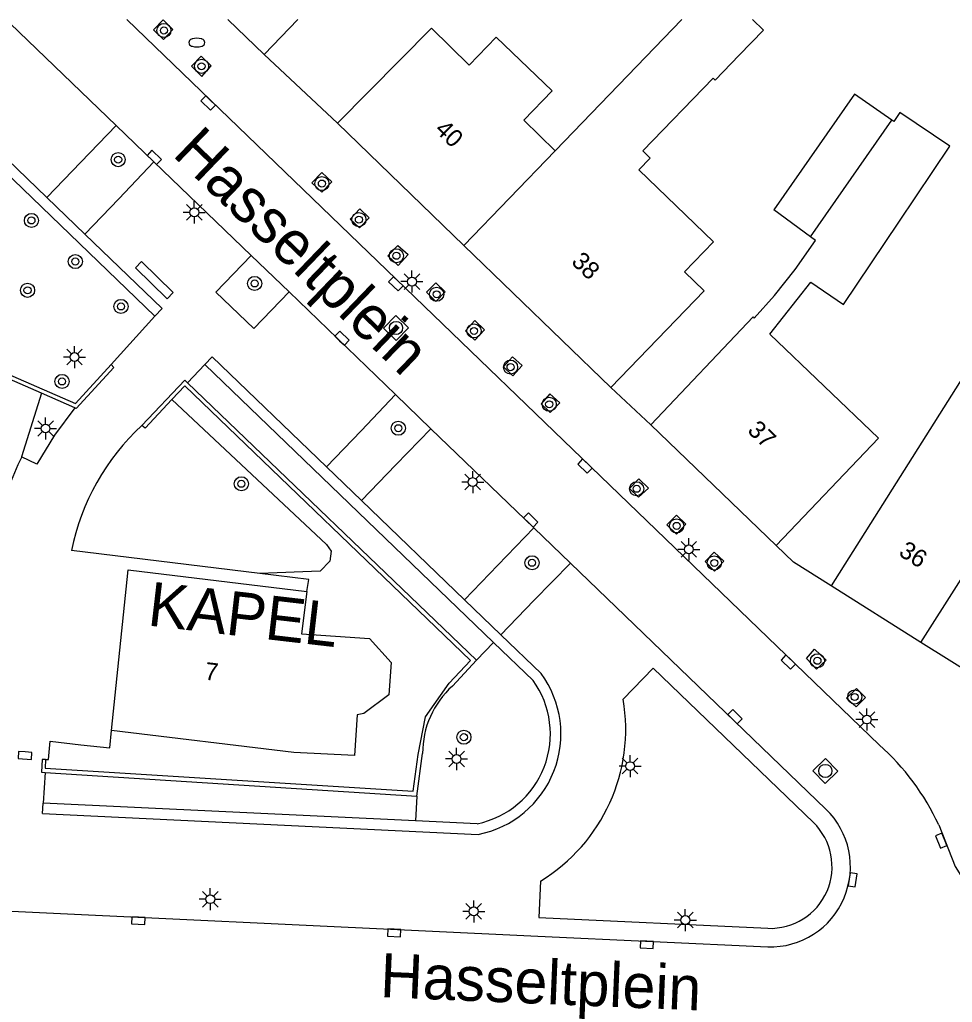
# Model space of a CAD drawing. Extents: x 132573 to 132944, y 398226 to 398676.
# Drawn here: x 132601.1 to 132654, y 398620.6 to 398676.3 of the extents above; entities that cross this region are included whole.
import ezdxf

# ---------------------------------------------------------------- set-up
doc = ezdxf.new("R2010")
doc.units = 0
for name, color, linetype in [('gg-afsc-muur', 7, 'Continuous'), ('gg-anno-huisnummerreeks BGT', 7, 'Continuous'), ('gg-anno-openbare ruimte label', 7, 'Continuous'), ('gg-bbg-gedigitaliseerde bebouwing', 7, 'Continuous'), ('gg-bbg-hoofdgebouw', 7, 'Continuous'), ('gg-bbg-tussenscheiding', 7, 'Continuous'), ('gg-knt-verharding', 7, 'Continuous'), ('gg-knt-verharding nz', 7, 'Continuous'), ('gt-anno-naam bijzondere bebouwing', 7, 'Continuous'), ('gt-grn-groengrens', 7, 'Continuous'), ('gt-symb-boom', 7, 'Continuous'), ('gt-symb-brandkraan', 7, 'Continuous'), ('gt-symb-kolk', 7, 'Continuous'), ('gt-symb-lichtmast', 7, 'Continuous'), ('gt-symb-rioolschacht', 7, 'Continuous')]:
    doc.layers.add(name, color=color, linetype=linetype)

msp = doc.modelspace()

# ---------------------------------------------------------------- linework, layer by layer
at = {"layer": 'gg-afsc-muur'}
for p, q in [((132626.969, 398640.013), (132610.591, 398655.743)), ((132604.184, 398654.336), (132602.3, 398655.159)), ((132625.614, 398638.552), (132626.969, 398640.013)), ((132623.589, 398632.31), (132623.919, 398634.733)), ((132602.5, 398633.653), (132623.589, 398632.31))]:
    msp.add_line(p, q, dxfattribs=at)
for points in [[(132581.916, 398656.875), (132582.123, 398657.394), (132586.774, 398662.172), (132604.239, 398654.571), (132606.249, 398656.783)], [(132602.3, 398655.159), (132586.814, 398661.924), (132582.315, 398657.245), (132580.926, 398653.711)], [(132606.249, 398656.783), (132606.396, 398656.624), (132604.276, 398654.296), (132604.184, 398654.336)], [(132602.536, 398634.387), (132602.516, 398633.899), (132623.377, 398632.584), (132623.666, 398634.661), (132624.092, 398636.807), (132625.425, 398638.709), (132626.629, 398640.007), (132610.43, 398655.572), (132609.699, 398654.797)], [(132610.591, 398655.743), (132610.43, 398655.897), (132607.998, 398653.329)], [(132609.699, 398654.797), (132608.176, 398653.182), (132607.998, 398653.329)], [(132602.536, 398634.387), (132602.332, 398634.387), (132602.292, 398633.666), (132602.5, 398633.653)]]:
    msp.add_lwpolyline(points, dxfattribs=at)
msp.add_arc((132629.062, 398634.736), 5.143, 132.0985, 180.035, dxfattribs=at)
at = {"layer": 'gg-bbg-gedigitaliseerde bebouwing'}
for p, q in [((132614.93, 398674.36), (132616.85, 398676.345)), ((132638.618, 398676.345), (132631.446, 398668.911)), ((132624.417, 398675.868), (132626.555, 398673.756)), ((132636.196, 398667.835), (132640.429, 398663.742)), ((132649.785, 398652.617), (132643.613, 398658.502))]:
    msp.add_line(p, q, dxfattribs=at)
for points in [[(132641.881, 398674.333), (132643.255, 398675.754), (132642.644, 398676.345)], [(132631.446, 398668.911), (132629.658, 398670.636), (132631.269, 398672.306), (132628.103, 398675.36), (132626.555, 398673.756)], [(132636.196, 398667.835), (132636.833, 398668.494), (132636.416, 398668.896), (132640.398, 398673.026), (132640.513, 398672.915), (132641.881, 398674.333)], [(132650.937, 398664.862), (132653.837, 398669.167), (132651.002, 398671.077), (132650.655, 398670.563), (132650.54, 398670.643)], [(132643.613, 398658.502), (132645.936, 398661.46), (132647.795, 398660.198), (132650.937, 398664.862)], [(132652.19, 398641.02), (132656.49, 398647.791), (132654.634, 398648.964), (132658.362, 398654.86), (132657.928, 398655.134), (132658.552, 398656.122), (132657.428, 398656.832), (132656.857, 398655.928), (132655.156, 398657.003), (132647.1, 398644.24)]]:
    msp.add_lwpolyline(points, dxfattribs=at)
at = {"layer": 'gg-bbg-hoofdgebouw'}
for p, q in [((132614.93, 398674.36), (132612.878, 398676.345)), ((132619.087, 398670.473), (132624.417, 398675.868)), ((132626.257, 398663.533), (132619.087, 398670.473)), ((132645.924, 398664.027), (132643.854, 398665.559)), ((132634.59, 398655.48), (132626.257, 398663.533)), ((132643.974, 398646.522), (132636.86, 398653.36)), ((132643.974, 398646.522), (132649.785, 398652.617)), ((132652.19, 398641.02), (132647.1, 398644.24))]:
    msp.add_line(p, q, dxfattribs=at)
for points in [[(132650.54, 398670.643), (132648.429, 398672.116), (132643.854, 398665.559)], [(132634.59, 398655.48), (132639.885, 398660.973), (132638.776, 398662.042), (132640.429, 398663.742)], [(132636.86, 398653.36), (132642.669, 398659.484), (132642.738, 398659.418), (132643.88, 398660.7), (132645.065, 398662.167), (132646.206, 398663.818), (132645.924, 398664.027)], [(132606.27, 398636.02), (132607.21, 398645.14), (132617.36, 398643.92)], [(132617.36, 398643.92), (132617.05, 398641.51), (132620.91, 398641.24), (132622.14, 398639.89), (132622, 398638.05), (132620.59, 398637), (132620.21, 398636.92), (132620.06, 398634.61), (132616.62, 398634.79), (132606.27, 398636.02)]]:
    msp.add_lwpolyline(points, dxfattribs=at)
at = {"layer": 'gg-bbg-tussenscheiding'}
for p, q in [((132645.924, 398664.027), (132650.54, 398670.643)), ((132631.446, 398668.911), (132626.257, 398663.533))]:
    msp.add_line(p, q, dxfattribs=at)
at = {"layer": 'gg-knt-verharding'}
for p, q in [((132600.53, 398676.126), (132606.54, 398670.339)), ((132607.145, 398676.345), (132649.82, 398635.22)), ((132619.087, 398670.473), (132614.93, 398674.36)), ((132596.587, 398672.048), (132602.603, 398666.258)), ((132604.538, 398668.268), (132606.54, 398670.339)), ((132606.54, 398670.339), (132608.669, 398668.288)), ((132604.538, 398668.268), (132602.603, 398666.258)), ((132608.669, 398668.288), (132606.693, 398666.186)), ((132608.669, 398668.288), (132614.197, 398662.965)), ((132602.603, 398666.258), (132604.762, 398664.18)), ((132606.693, 398666.186), (132604.762, 398664.18)), ((132604.762, 398664.18), (132609.141, 398659.964)), ((132614.197, 398662.965), (132616.343, 398660.899)), ((132616.343, 398660.899), (132622.378, 398655.087)), ((132608.737, 398659.52), (132609.141, 398659.964)), ((132606.249, 398656.783), (132608.737, 398659.52)), ((132611.575, 398656.787), (132611.987, 398657.223)), ((132618.47, 398650.983), (132611.987, 398657.223)), ((132610.591, 398655.743), (132611.575, 398656.787)), ((132634.59, 398655.48), (132636.86, 398653.36)), ((132620.431, 398653.02), (132622.378, 398655.087)), ((132622.378, 398655.087), (132624.397, 398653.143)), ((132620.431, 398653.02), (132618.47, 398650.983)), ((132624.397, 398653.143), (132622.397, 398651.093)), ((132624.397, 398653.143), (132630.228, 398647.528)), ((132620.453, 398649.074), (132618.47, 398650.983)), ((132622.397, 398651.093), (132620.453, 398649.074)), ((132626.299, 398643.446), (132620.453, 398649.074)), ((132628.182, 398645.402), (132630.228, 398647.528)), ((132630.228, 398647.528), (132632.317, 398645.516)), ((132614.689, 398644.939), (132604.005, 398646.24)), ((132628.182, 398645.402), (132626.299, 398643.446)), ((132632.317, 398645.516), (132630.235, 398643.407)), ((132646.8, 398631.57), (132632.317, 398645.516)), ((132628.362, 398641.461), (132626.299, 398643.446)), ((132630.235, 398643.407), (132628.362, 398641.461)), ((132630.641, 398639.267), (132628.362, 398641.461)), ((132656.431, 398638.37), (132652.19, 398641.02)), ((132602.5, 398633.653), (132602.39, 398631.917)), ((132602.352, 398631.318), (132602.39, 398631.917)), ((132602.352, 398631.318), (132627.07, 398630.14)), ((132630.61, 398627.49), (132630.51, 398625.42)), ((132630.51, 398625.42), (132643.502, 398624.81)), ((132630.462, 398624.371), (132643.504, 398623.758))]:
    msp.add_line(p, q, dxfattribs=at)
for points in [[(132609.222, 398675.228), (132608.658, 398675.768), (132609.201, 398676.328), (132609.745, 398675.793), (132609.222, 398675.228)], [(132611.397, 398673.13), (132611.932, 398673.727), (132611.35, 398674.27), (132610.817, 398673.703), (132611.397, 398673.13)], [(132617.637, 398667.088), (132618.198, 398666.567), (132618.769, 398667.145), (132618.197, 398667.68), (132617.637, 398667.088)], [(132619.804, 398665.035), (132620.354, 398665.615), (132620.888, 398665.099), (132620.343, 398664.535), (132619.804, 398665.035)], [(132621.946, 398662.943), (132622.514, 398663.542), (132623.094, 398663.031), (132622.543, 398662.406), (132621.946, 398662.943)], [(132616.343, 398660.899), (132614.346, 398658.829), (132612.188, 398660.895), (132614.197, 398662.965)], [(132624.136, 398660.881), (132624.664, 398660.364), (132625.193, 398660.904), (132624.665, 398661.422), (132624.136, 398660.881)], [(132626.353, 398658.7), (132626.882, 398659.28), (132627.436, 398658.757), (132626.882, 398658.171), (132626.353, 398658.7)], [(132628.504, 398656.653), (132629.02, 398657.219), (132629.562, 398656.73), (132629.034, 398656.144), (132628.504, 398656.653)], [(132630.645, 398654.563), (132631.164, 398654.062), (132631.698, 398654.615), (132631.142, 398655.115), (132630.645, 398654.563)], [(132604.184, 398654.336), (132603.035, 398652.785), (132602.039, 398651.132), (132601.175, 398651.558)], [(132635.655, 398649.748), (132636.179, 398650.298), (132636.735, 398649.778), (132636.177, 398649.264), (132635.655, 398649.748)], [(132637.778, 398647.694), (132638.318, 398648.251), (132638.858, 398647.728), (132638.318, 398647.171), (132637.778, 398647.694)], [(132647.1, 398644.24), (132644.96, 398645.58), (132643.974, 398646.522)], [(132639.947, 398645.605), (132640.48, 398645.06), (132641.015, 398645.629), (132640.461, 398646.151), (132639.947, 398645.605)], [(132617.36, 398643.92), (132617.474, 398644.6), (132614.689, 398644.939)], [(132645.691, 398640.113), (132646.16, 398640.648), (132646.811, 398640.024), (132646.275, 398639.514), (132645.691, 398640.113)], [(132646.09, 398630.81), (132637.01, 398639.57), (132635.3, 398637.798)], [(132647.976, 398637.865), (132648.512, 398637.373), (132649.046, 398637.896), (132648.535, 398638.415), (132647.976, 398637.865)], [(132604.528, 398635.224), (132606.169, 398635.04), (132606.27, 398636.02)], [(132602.536, 398634.387), (132602.691, 398634.386), (132602.8, 398635.418), (132604.528, 398635.224)], [(132653.2, 398630.67), (132654.14, 398628.31), (132656.12, 398625.15)], [(132595.275, 398623.27), (132595.4, 398626.02), (132630.462, 398624.371)]]:
    msp.add_lwpolyline(points, dxfattribs=at)
for centre, radius, start, end in [((132616.971, 398643.606), 13.23, 132.7013, 168.5165), ((132617.338, 398643.698), 17.972, 154.0661, 166.8003), ((132625.971, 398635.832), 5.797, 280.9241, 36.3394), ((132625.374, 398636.093), 10.071, 301.3235, 9.7467), ((132640.708, 398624.921), 13.751, 24.7137, 48.5005), ((132643.647, 398628.299), 4.543, 268.1983, 46.0505), ((132643.653, 398628.303), 3.496, 267.5301, 45.8056)]:
    msp.add_arc(centre, radius, start, end, dxfattribs=at)
at = {"layer": 'gg-knt-verharding nz'}
msp.add_lwpolyline([(132609.426, 398660.505), (132609.767, 398660.868), (132607.969, 398662.628), (132607.629, 398662.265), (132609.426, 398660.505)], dxfattribs=at)
at = {"layer": 'gt-grn-groengrens'}
for p, q in [((132627.946, 398641.028), (132611.575, 398656.787)), ((132602.3, 398655.159), (132601.175, 398651.558)), ((132626.969, 398640.013), (132627.946, 398641.028)), ((132630.187, 398638.871), (132627.946, 398641.028)), ((132623.589, 398632.31), (132623.522, 398630.91)), ((132623.522, 398630.91), (132602.39, 398631.917)), ((132627.025, 398630.743), (132623.522, 398630.91))]:
    msp.add_line(p, q, dxfattribs=at)
for points in [[(132608.737, 398659.52), (132594.261, 398673.455), (132580.619, 398659.429)], [(132609.699, 398654.797), (132618.478, 398646.576), (132618.732, 398646.208), (132618.665, 398645.628), (132618.106, 398645.068), (132614.689, 398644.939)]]:
    msp.add_lwpolyline(points, dxfattribs=at)
msp.add_arc((132625.972, 398635.832), 5.197, 281.6925, 35.7929, dxfattribs=at)
at = {"layer": 'gt-symb-boom'}
for centre, radius in [((132609.246, 398675.731), 0.4), ((132609.246, 398675.731), 0.2), ((132611.378, 398673.7), 0.4), ((132611.378, 398673.7), 0.2), ((132606.65, 398668.406), 0.4), ((132606.65, 398668.406), 0.2), ((132618.207, 398667.049), 0.4), ((132618.207, 398667.049), 0.2), ((132601.731, 398664.957), 0.4), ((132601.731, 398664.957), 0.2), ((132620.305, 398665.002), 0.4), ((132620.305, 398665.002), 0.2), ((132622.438, 398662.953), 0.4), ((132604.22, 398662.628), 0.4), ((132604.22, 398662.628), 0.2), ((132622.438, 398662.953), 0.2), ((132614.392, 398661.385), 0.4), ((132614.392, 398661.385), 0.2), ((132601.508, 398660.994), 0.4), ((132601.508, 398660.994), 0.2), ((132624.717, 398660.77), 0.4), ((132624.717, 398660.77), 0.2), ((132606.809, 398660.08), 0.4), ((132606.809, 398660.08), 0.2), ((132626.837, 398658.69), 0.4), ((132626.837, 398658.69), 0.2), ((132628.91, 398656.637), 0.4), ((132628.91, 398656.637), 0.2), ((132603.465, 398655.825), 0.4), ((132603.465, 398655.825), 0.2), ((132631.102, 398654.532), 0.4), ((132631.102, 398654.532), 0.2), ((132622.543, 398653.172), 0.4), ((132622.543, 398653.172), 0.2), ((132613.639, 398650.023), 0.4), ((132613.639, 398650.023), 0.2), ((132636.063, 398649.739), 0.4), ((132636.063, 398649.739), 0.2), ((132638.332, 398647.635), 0.4), ((132638.332, 398647.635), 0.2), ((132630.128, 398645.54), 0.4), ((132640.468, 398645.532), 0.4), ((132630.128, 398645.54), 0.2), ((132640.468, 398645.532), 0.2), ((132646.32, 398639.983), 0.4), ((132646.32, 398639.983), 0.2), ((132648.435, 398637.931), 0.4), ((132648.435, 398637.931), 0.2), ((132626.261, 398635.651), 0.4), ((132626.261, 398635.651), 0.2)]:
    msp.add_circle(centre, radius, dxfattribs=at)
at = {"layer": 'gt-symb-brandkraan'}
for centre, radius, start, end in [((132610.871, 398675.045), 0.206, 107.5669, 252.4331), ((132611.714, 398672.381), 3, 106.892, 107.5669), ((132611.115, 398674.354), 0.938, 73.108, 106.892), ((132610.516, 398672.381), 3, 72.4331, 73.108), ((132611.359, 398675.045), 0.206, 287.567, 72.4331), ((132611.714, 398677.709), 3, 252.4331, 253.108), ((132611.115, 398675.736), 0.938, 253.108, 286.8921), ((132610.516, 398677.709), 3, 286.8921, 287.567)]:
    msp.add_arc(centre, radius, start, end, dxfattribs=at)
at = {"layer": 'gt-symb-kolk'}
for points in [[(132611.897, 398671.763), (132611.627, 398672.024), (132611.349, 398671.736), (132611.889, 398671.215), (132612.167, 398671.502), (132611.897, 398671.763)], [(132608.562, 398668.39), (132608.833, 398668.131), (132609.109, 398668.42), (132608.567, 398668.938), (132608.291, 398668.649), (132608.562, 398668.39)], [(132622.541, 398661.508), (132622.271, 398661.768), (132621.993, 398661.48), (132622.533, 398660.96), (132622.811, 398661.248), (132622.541, 398661.508)], [(132619.211, 398658.137), (132619.481, 398657.877), (132619.759, 398658.166), (132619.218, 398658.685), (132618.941, 398658.397), (132619.211, 398658.137)], [(132633.268, 398651.171), (132632.998, 398651.431), (132632.72, 398651.143), (132633.26, 398650.623), (132633.538, 398650.911), (132633.268, 398651.171)], [(132629.919, 398647.824), (132630.189, 398647.563), (132630.467, 398647.851), (132629.927, 398648.372), (132629.649, 398648.085), (132629.919, 398647.824)], [(132644.802, 398640.054), (132644.532, 398640.315), (132644.254, 398640.027), (132644.794, 398639.506), (132645.072, 398639.793), (132644.802, 398640.054)], [(132641.503, 398636.67), (132641.773, 398636.41), (132642.051, 398636.698), (132641.511, 398637.218), (132641.233, 398636.93), (132641.503, 398636.67)], [(132601.378, 398634.811), (132601.004, 398634.836), (132600.977, 398634.437), (132601.726, 398634.387), (132601.752, 398634.786), (132601.378, 398634.811)], [(132653.522, 398629.853), (132653.381, 398630.2), (132653.01, 398630.049), (132653.293, 398629.355), (132653.663, 398629.506), (132653.522, 398629.853)], [(132648.12, 398627.595), (132648.061, 398627.225), (132648.456, 398627.162), (132648.574, 398627.903), (132648.179, 398627.965), (132648.12, 398627.595)], [(132607.805, 398625.437), (132607.43, 398625.455), (132607.411, 398625.056), (132608.16, 398625.019), (132608.18, 398625.419), (132607.805, 398625.437)], [(132622.315, 398624.754), (132621.94, 398624.772), (132621.921, 398624.372), (132622.67, 398624.336), (132622.69, 398624.736), (132622.315, 398624.754)], [(132636.648, 398624.08), (132636.273, 398624.097), (132636.256, 398623.697), (132637.005, 398623.664), (132637.023, 398624.063), (132636.648, 398624.08)]]:
    msp.add_lwpolyline(points, dxfattribs=at)
at = {"layer": 'gt-symb-lichtmast'}
for p, q in [((132610.97, 398665.666), (132610.97, 398666.041)), ((132610.72, 398665.416), (132610.345, 398665.416)), ((132610.793, 398665.593), (132610.528, 398665.858)), ((132611.147, 398665.593), (132611.412, 398665.858)), ((132611.22, 398665.416), (132611.595, 398665.416)), ((132610.793, 398665.239), (132610.528, 398664.974)), ((132610.97, 398665.166), (132610.97, 398664.791)), ((132611.412, 398664.974), (132611.147, 398665.239)), ((132623.317, 398661.736), (132623.317, 398662.111)), ((132623.14, 398661.663), (132622.875, 398661.928)), ((132623.494, 398661.663), (132623.759, 398661.928)), ((132623.067, 398661.486), (132622.692, 398661.486)), ((132623.14, 398661.309), (132622.875, 398661.044)), ((132623.317, 398661.236), (132623.317, 398660.861)), ((132623.759, 398661.044), (132623.494, 398661.309)), ((132623.567, 398661.486), (132623.942, 398661.486)), ((132603.994, 398657.386), (132603.729, 398657.651)), ((132604.171, 398657.459), (132604.171, 398657.834)), ((132604.348, 398657.386), (132604.613, 398657.651)), ((132603.921, 398657.209), (132603.546, 398657.209)), ((132604.421, 398657.209), (132604.796, 398657.209)), ((132603.994, 398657.032), (132603.729, 398656.767)), ((132604.171, 398656.959), (132604.171, 398656.584)), ((132604.613, 398656.767), (132604.348, 398657.032)), ((132602.532, 398653.405), (132602.532, 398653.78)), ((132602.282, 398653.155), (132601.907, 398653.155)), ((132602.355, 398653.332), (132602.09, 398653.597)), ((132602.709, 398653.332), (132602.974, 398653.597)), ((132602.782, 398653.155), (132603.157, 398653.155)), ((132602.355, 398652.978), (132602.09, 398652.713)), ((132602.532, 398652.905), (132602.532, 398652.53)), ((132602.974, 398652.713), (132602.709, 398652.978)), ((132626.586, 398650.296), (132626.321, 398650.561)), ((132626.763, 398650.369), (132626.763, 398650.744)), ((132626.94, 398650.296), (132627.205, 398650.561)), ((132626.513, 398650.119), (132626.138, 398650.119)), ((132626.586, 398649.942), (132626.321, 398649.677)), ((132626.763, 398649.869), (132626.763, 398649.494)), ((132627.205, 398649.677), (132626.94, 398649.942)), ((132627.013, 398650.119), (132627.388, 398650.119)), ((132638.847, 398646.48), (132638.582, 398646.745)), ((132639.024, 398646.553), (132639.024, 398646.928)), ((132639.201, 398646.48), (132639.466, 398646.745)), ((132638.774, 398646.303), (132638.399, 398646.303)), ((132638.847, 398646.126), (132638.582, 398645.861)), ((132639.024, 398646.053), (132639.024, 398645.678)), ((132639.466, 398645.861), (132639.201, 398646.126)), ((132639.274, 398646.303), (132639.649, 398646.303)), ((132648.948, 398636.827), (132648.683, 398637.092)), ((132649.125, 398636.9), (132649.125, 398637.275)), ((132649.302, 398636.827), (132649.567, 398637.092)), ((132648.875, 398636.65), (132648.5, 398636.65)), ((132648.948, 398636.473), (132648.683, 398636.208)), ((132649.567, 398636.208), (132649.302, 398636.473)), ((132649.375, 398636.65), (132649.75, 398636.65)), ((132649.125, 398636.4), (132649.125, 398636.025)), ((132625.671, 398634.59), (132625.406, 398634.855)), ((132625.848, 398634.663), (132625.848, 398635.038)), ((132626.025, 398634.59), (132626.29, 398634.855)), ((132625.598, 398634.413), (132625.223, 398634.413)), ((132625.671, 398634.236), (132625.406, 398633.971)), ((132626.29, 398633.971), (132626.025, 398634.236)), ((132626.098, 398634.413), (132626.473, 398634.413)), ((132635.513, 398634.187), (132635.248, 398634.452)), ((132635.69, 398634.26), (132635.69, 398634.635)), ((132635.867, 398634.187), (132636.132, 398634.452)), ((132625.848, 398634.163), (132625.848, 398633.788)), ((132635.44, 398634.01), (132635.065, 398634.01)), ((132635.513, 398633.833), (132635.248, 398633.568)), ((132635.69, 398633.76), (132635.69, 398633.385)), ((132636.132, 398633.568), (132635.867, 398633.833)), ((132635.94, 398634.01), (132636.315, 398634.01)), ((132611.876, 398626.71), (132611.876, 398627.085)), ((132611.626, 398626.46), (132611.251, 398626.46)), ((132611.699, 398626.637), (132611.434, 398626.902)), ((132612.053, 398626.637), (132612.318, 398626.902)), ((132612.126, 398626.46), (132612.501, 398626.46)), ((132626.821, 398626.022), (132626.821, 398626.397)), ((132611.699, 398626.283), (132611.434, 398626.018)), ((132611.876, 398626.21), (132611.876, 398625.835)), ((132612.318, 398626.018), (132612.053, 398626.283)), ((132626.644, 398625.949), (132626.379, 398626.214)), ((132626.998, 398625.949), (132627.263, 398626.214)), ((132638.825, 398625.529), (132638.825, 398625.904)), ((132626.571, 398625.772), (132626.196, 398625.772)), ((132626.644, 398625.595), (132626.379, 398625.33)), ((132626.821, 398625.522), (132626.821, 398625.147)), ((132627.263, 398625.33), (132626.998, 398625.595)), ((132627.071, 398625.772), (132627.446, 398625.772)), ((132638.575, 398625.279), (132638.2, 398625.279)), ((132638.648, 398625.456), (132638.383, 398625.721)), ((132639.002, 398625.456), (132639.267, 398625.721)), ((132639.075, 398625.279), (132639.45, 398625.279)), ((132638.648, 398625.102), (132638.383, 398624.837)), ((132638.825, 398625.029), (132638.825, 398624.654)), ((132639.267, 398624.837), (132639.002, 398625.102))]:
    msp.add_line(p, q, dxfattribs=at)
for centre in [(132610.97, 398665.416), (132623.317, 398661.486), (132604.171, 398657.209), (132602.532, 398653.155), (132626.763, 398650.119), (132639.024, 398646.303), (132649.125, 398636.65), (132625.848, 398634.413), (132635.69, 398634.01), (132611.876, 398626.46), (132626.821, 398625.772), (132638.825, 398625.279)]:
    msp.add_circle(centre, 0.25, dxfattribs=at)
at = {"layer": 'gt-symb-rioolschacht'}
for points in [[(132623.12, 398658.868), (132622.404, 398659.566), (132621.706, 398658.85), (132622.422, 398658.152)], [(132647.475, 398633.722), (132646.779, 398634.44), (132646.061, 398633.744), (132646.757, 398633.026)]]:
    msp.add_lwpolyline(points, close=True, dxfattribs=at)
for centre in [(132622.413, 398658.859), (132646.768, 398633.733)]:
    msp.add_circle(centre, 0.375, dxfattribs=at)

# ---------------------------------------------------------------- texts
at = {"layer": 'gg-anno-huisnummerreeks BGT'}
for s, rotation, p in [('40', 316, (132624.556, 398670.048)), ('38', 316, (132632.307, 398662.553)), ('37', 316.1, (132642.297, 398652.991)), ('36', 327.7, (132650.871, 398645.996)), ('7', 353.2, (132611.522, 398638.92))]:
    msp.add_text(s, height=1, rotation=rotation, dxfattribs=at).set_placement(p)
at = {"layer": 'gg-anno-openbare ruimte label'}
for rotation, p in [(316.1, (132609.674, 398668.665)), (357.6, (132621.482, 398620.912))]:
    msp.add_text('Hasseltplein', height=2.5, rotation=rotation, dxfattribs=at).set_placement(p)
at = {"layer": 'gt-anno-naam bijzondere bebouwing'}
msp.add_text('KAPEL', height=2.5, rotation=353.394, dxfattribs=at).set_placement((132608.27, 398641.993))

doc.saveas('drawing.dxf')
